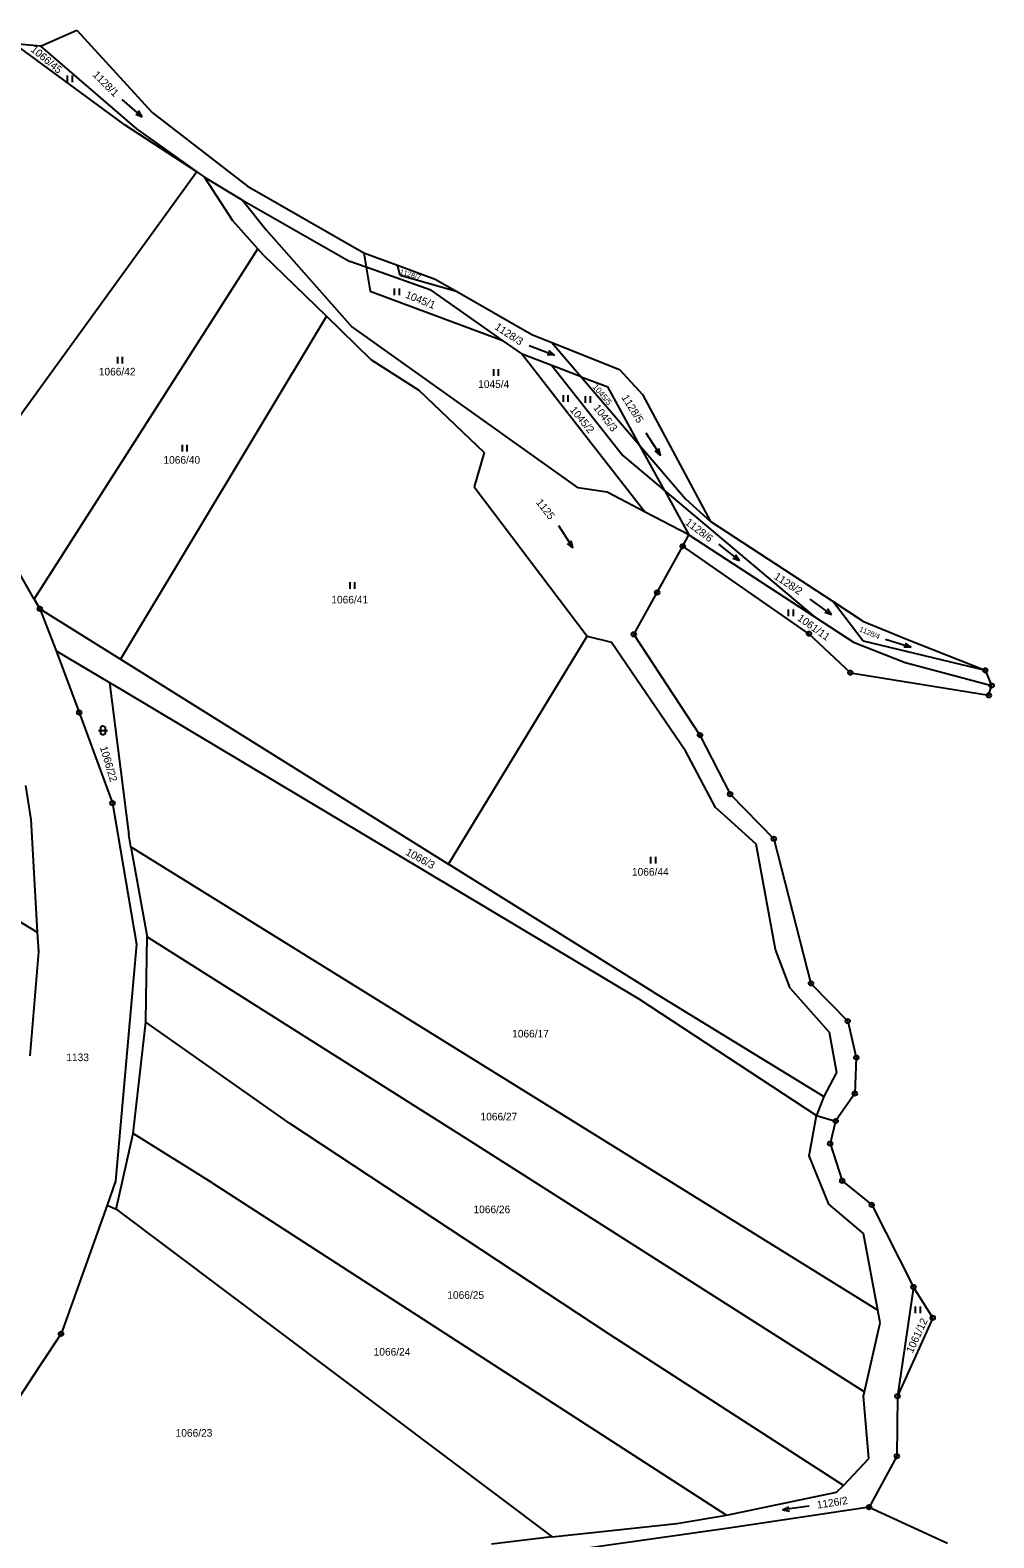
# Model space of a CAD drawing. Extents: x -794142 to -791199, y -1109267 to -1105626.
# Drawn here: x -791448.6 to -791232.9, y -1108817.8 to -1108480.5 of the extents above; entities that cross this region are included whole.
import ezdxf

# ---------------------------------------------------------------- set-up
doc = ezdxf.new("R2010")
doc.units = 0
for name, color, linetype in [('Vrstva 1', 7, 'Continuous'), ('Vrstva 14', 7, 'Continuous'), ('Vrstva 23', 7, 'Continuous'), ('Vrstva 28', 7, 'Continuous'), ('Vrstva 4', 7, 'Continuous')]:
    doc.layers.add(name, color=color, linetype=linetype)

msp = doc.modelspace()

# ---------------------------------------------------------------- linework, layer by layer
at = {"layer": 'Vrstva 1'}
for p, q in [((-791427.3, -1108501.83), (-791452.02, -1108483.63)), ((-791446.22, -1108484.1), (-791424.74, -1108502.61)), ((-791411.23, -1108512.26), (-791427.3, -1108501.83)), ((-791424.74, -1108502.61), (-791411.23, -1108512.26)), ((-791411.23, -1108512.26), (-791462.13, -1108582.4)), ((-791411.23, -1108512.26), (-791409.56, -1108513.46)), ((-791409.56, -1108513.46), (-791401.01, -1108518.59)), ((-791403.21, -1108523.17), (-791409.56, -1108513.46)), ((-791401.01, -1108518.59), (-791395.75, -1108525.23)), ((-791401.01, -1108518.59), (-791377, -1108532.27)), ((-791397.61, -1108529.42), (-791403.21, -1108523.17)), ((-791395.75, -1108525.23), (-791376.56, -1108546.87)), ((-791447.63, -1108607.79), (-791397.61, -1108529.42)), ((-791396.4, -1108530.77), (-791397.61, -1108529.42)), ((-791382.28, -1108544.53), (-791396.4, -1108530.77)), ((-791373.88, -1108530.37), (-791373.36, -1108533.57)), ((-791373.36, -1108533.57), (-791377, -1108532.27)), ((-791358.93, -1108538.72), (-791373.36, -1108533.57)), ((-791373.36, -1108533.57), (-791372.49, -1108538.94)), ((-791365.8, -1108535.45), (-791366.34, -1108533.14)), ((-791352.97, -1108539.08), (-791365.8, -1108535.45)), ((-791372.49, -1108538.94), (-791342.99, -1108549.86)), ((-791358.93, -1108538.72), (-791342.99, -1108549.86)), ((-791382.28, -1108544.53), (-791428.37, -1108621.22)), ((-791372.33, -1108554.23), (-791382.28, -1108544.53)), ((-791376.56, -1108546.87), (-791325.99, -1108582.88)), ((-791342.99, -1108549.86), (-791338.45, -1108553.03)), ((-791331.82, -1108550.39), (-791325.27, -1108558.06)), ((-791372.33, -1108554.23), (-791361.56, -1108561.06)), ((-791331.87, -1108555.54), (-791338.45, -1108553.03)), ((-791338.45, -1108553.03), (-791323.6, -1108572.11)), ((-791331.87, -1108555.54), (-791315.93, -1108575.68)), ((-791325.27, -1108558.06), (-791331.87, -1108555.54)), ((-791361.56, -1108561.06), (-791346.94, -1108574.99)), ((-791325.27, -1108558.06), (-791312.12, -1108573.45)), ((-791325.27, -1108558.06), (-791319.32, -1108560.33)), ((-791312.12, -1108573.45), (-791319.32, -1108560.33)), ((-791323.6, -1108572.11), (-791310.94, -1108588.33)), ((-791306.58, -1108583.55), (-791312.12, -1108573.45)), ((-791312.12, -1108573.45), (-791301.92, -1108585.39)), ((-791346.94, -1108574.99), (-791349.24, -1108582.69)), ((-791315.93, -1108575.68), (-791306.58, -1108583.55)), ((-791447.63, -1108607.79), (-791462.13, -1108582.4)), ((-791349.24, -1108582.69), (-791323.91, -1108616.12)), ((-791319.49, -1108583.87), (-791325.99, -1108582.88)), ((-791310.94, -1108588.33), (-791319.49, -1108583.87)), ((-791306.58, -1108583.55), (-791301.16, -1108593.44)), ((-791306.58, -1108583.55), (-791273.14, -1108611.72)), ((-791301.16, -1108593.44), (-791310.94, -1108588.33)), ((-791301.92, -1108585.39), (-791296.3, -1108590.48)), ((-791302.56, -1108595.98), (-791301.16, -1108593.44)), ((-791301.16, -1108593.44), (-791273.14, -1108611.72)), ((-791447.63, -1108607.79), (-791446.38, -1108609.97)), ((-791268.84, -1108608.45), (-791262.15, -1108617.17)), ((-791446.38, -1108609.97), (-791428.37, -1108621.22)), ((-791446.38, -1108609.97), (-791442.72, -1108619.38)), ((-791273.14, -1108611.72), (-791264.35, -1108617.45)), ((-791354.93, -1108667.11), (-791323.91, -1108616.12)), ((-791323.91, -1108616.12), (-791318.45, -1108617.47)), ((-791318.45, -1108617.47), (-791302.04, -1108641.62)), ((-791264.35, -1108617.45), (-791252.76, -1108621.95)), ((-791262.15, -1108617.17), (-791234.86, -1108623.73)), ((-791442.72, -1108619.38), (-791430.81, -1108626.43)), ((-791442.72, -1108619.38), (-791437.57, -1108633.18)), ((-791428.37, -1108621.22), (-791354.93, -1108667.11)), ((-791252.76, -1108621.95), (-791248.84, -1108623)), ((-791248.84, -1108623), (-791233.44, -1108627.13)), ((-791430.81, -1108626.43), (-791427.9, -1108628.17)), ((-791430.81, -1108626.43), (-791426.49, -1108660.51)), ((-791427.9, -1108628.17), (-791312.39, -1108697.23)), ((-791532.37, -1108630.01), (-791446.95, -1108682.34)), ((-791437.57, -1108633.18), (-791430.12, -1108653.46)), ((-791295.18, -1108654.41), (-791302.04, -1108641.62)), ((-791449.61, -1108649.48), (-791448.39, -1108657.12)), ((-791430.12, -1108653.46), (-791424.78, -1108685.01)), ((-791292.45, -1108656.87), (-791295.18, -1108654.41)), ((-791448.39, -1108657.12), (-791446.95, -1108682.34)), ((-791286.09, -1108662.61), (-791292.45, -1108656.87)), ((-791426, -1108663.21), (-791426.49, -1108660.51)), ((-791426, -1108663.21), (-791422.34, -1108683.38)), ((-791426, -1108663.21), (-791258.88, -1108766.87)), ((-791281.83, -1108686.19), (-791286.09, -1108662.61)), ((-791309.12, -1108695.74), (-791354.93, -1108667.11)), ((-791446.95, -1108682.34), (-791446.7, -1108686.74)), ((-791424.78, -1108685.01), (-791429.43, -1108738.03)), ((-791422.56, -1108697.06), (-791422.34, -1108683.38)), ((-791422.34, -1108683.38), (-791350.23, -1108728.91)), ((-791278.5, -1108694.84), (-791281.83, -1108686.19)), ((-791446.7, -1108686.74), (-791448.66, -1108709.97)), ((-791309.12, -1108695.74), (-791270.97, -1108719.08)), ((-791278.5, -1108694.84), (-791269.76, -1108704.68)), ((-791422.64, -1108702.44), (-791422.56, -1108697.06)), ((-791312.39, -1108697.23), (-791272.6, -1108723.32)), ((-791425.51, -1108727.35), (-791422.64, -1108702.44)), ((-791390.48, -1108725.11), (-791422.64, -1108702.44)), ((-791269.76, -1108704.68), (-791268.17, -1108713.72)), ((-791268.17, -1108713.72), (-791270.97, -1108719.08)), ((-791270.97, -1108719.08), (-791272.6, -1108723.32)), ((-791318.75, -1108772.36), (-791390.48, -1108725.11)), ((-791274.25, -1108732.36), (-791272.6, -1108723.32)), ((-791272.6, -1108723.32), (-791268.34, -1108724.56)), ((-791429.33, -1108744.29), (-791425.51, -1108727.35)), ((-791407.81, -1108738.38), (-791425.51, -1108727.35)), ((-791350.23, -1108728.91), (-791261.91, -1108785.1)), ((-791269.88, -1108743.18), (-791274.25, -1108732.36)), ((-791429.43, -1108738.03), (-791431.31, -1108743.39)), ((-791407.81, -1108738.38), (-791292.77, -1108812.71)), ((-791431.31, -1108743.39), (-791441.64, -1108772.15)), ((-791431.31, -1108743.39), (-791429.33, -1108744.29)), ((-791262.09, -1108749.73), (-791269.88, -1108743.18)), ((-791429.33, -1108744.29), (-791331.75, -1108817.59)), ((-791258.88, -1108766.87), (-791262.09, -1108749.73)), ((-791250.93, -1108761.68), (-791254.49, -1108786.11)), ((-791258.35, -1108769.67), (-791258.88, -1108766.87)), ((-791261.91, -1108785.1), (-791258.35, -1108769.67)), ((-791446.31, -1108779.26), (-791441.64, -1108772.15)), ((-791266.58, -1108806.07), (-791318.75, -1108772.36)), ((-791459, -1108798.61), (-791446.31, -1108779.26)), ((-791262.14, -1108786.09), (-791261.91, -1108785.1)), ((-791260.91, -1108800.07), (-791262.14, -1108786.09)), ((-791266.58, -1108806.07), (-791260.91, -1108800.07)), ((-791292.77, -1108812.71), (-791268.14, -1108807.57)), ((-791268.14, -1108807.57), (-791266.58, -1108806.07)), ((-791260.86, -1108810.93), (-791292.25, -1108815.59)), ((-791303.85, -1108814.58), (-791292.77, -1108812.71)), ((-791331.75, -1108817.59), (-791345.32, -1108819.21)), ((-791292.25, -1108815.59), (-791338.01, -1108822.07)), ((-791331.75, -1108817.59), (-791303.85, -1108814.58))]:
    msp.add_line(p, q, dxfattribs=at)
at = {"layer": 'Vrstva 23'}
for p, q in [((-791440.16, -1108492.16), (-791440.16, -1108490.66)), ((-791439.16, -1108490.66), (-791439.16, -1108492.16)), ((-791428.016, -1108496.044), (-791423.483, -1108499.975)), ((-791423.483, -1108499.975), (-791424.944, -1108499.37)), ((-791423.483, -1108499.975), (-791424.289, -1108498.614)), ((-791367.02, -1108539.81), (-791367.02, -1108538.31)), ((-791366.02, -1108538.31), (-791366.02, -1108539.81)), ((-791336.871, -1108551.066), (-791331.268, -1108553.213)), ((-791428.95, -1108555.08), (-791428.95, -1108553.58)), ((-791427.95, -1108553.58), (-791427.95, -1108555.08)), ((-791331.268, -1108553.213), (-791332.848, -1108553.143)), ((-791331.268, -1108553.213), (-791332.49, -1108552.209)), ((-791344.81, -1108557.87), (-791344.81, -1108556.37)), ((-791343.81, -1108556.37), (-791343.81, -1108557.87)), ((-791329.26, -1108563.68), (-791329.26, -1108562.18)), ((-791328.26, -1108562.18), (-791328.26, -1108563.68)), ((-791324.27, -1108563.88), (-791324.27, -1108562.38)), ((-791323.27, -1108562.38), (-791323.27, -1108563.88)), ((-791310.789, -1108570.627), (-791307.51, -1108575.652)), ((-791414.48, -1108574.82), (-791414.48, -1108573.32)), ((-791413.48, -1108573.32), (-791413.48, -1108574.82)), ((-791307.51, -1108575.652), (-791308.748, -1108574.669)), ((-791307.51, -1108575.652), (-791307.911, -1108574.122)), ((-791330.379, -1108591.307), (-791327.1, -1108596.332)), ((-791327.1, -1108596.332), (-791327.501, -1108594.802)), ((-791327.1, -1108596.332), (-791328.338, -1108595.349)), ((-791294.578, -1108595.535), (-791289.861, -1108599.244)), ((-791289.861, -1108599.244), (-791290.731, -1108597.924)), ((-791289.861, -1108599.244), (-791291.349, -1108598.71)), ((-791376.96, -1108605.5), (-791376.96, -1108604)), ((-791375.96, -1108604), (-791375.96, -1108605.5)), ((-791274.119, -1108607.804), (-791269.24, -1108611.295)), ((-791278.85, -1108611.62), (-791278.85, -1108610.12)), ((-791277.85, -1108610.12), (-791277.85, -1108611.62)), ((-791269.24, -1108611.295), (-791270.751, -1108610.829)), ((-791269.24, -1108611.295), (-791270.169, -1108610.016)), ((-791257.176, -1108616.733), (-791251.463, -1108618.566)), ((-791251.463, -1108618.566), (-791253.044, -1108618.584)), ((-791251.463, -1108618.566), (-791252.738, -1108617.632)), ((-791433.27, -1108637.18), (-791431.27, -1108637.18)), ((-791432.77, -1108636.58), (-791432.67, -1108636.38)), ((-791432.77, -1108637.78), (-791432.77, -1108636.58)), ((-791432.67, -1108637.98), (-791432.77, -1108637.78)), ((-791432.67, -1108636.38), (-791432.57, -1108636.28)), ((-791432.57, -1108638.08), (-791432.67, -1108637.98)), ((-791432.57, -1108636.28), (-791432.37, -1108636.18)), ((-791432.37, -1108638.18), (-791432.57, -1108638.08)), ((-791432.37, -1108636.18), (-791432.17, -1108636.18)), ((-791432.17, -1108638.18), (-791432.37, -1108638.18)), ((-791432.17, -1108636.18), (-791431.97, -1108636.28)), ((-791431.97, -1108638.08), (-791432.17, -1108638.18)), ((-791431.97, -1108636.28), (-791431.87, -1108636.38)), ((-791431.87, -1108637.98), (-791431.97, -1108638.08)), ((-791431.87, -1108636.38), (-791431.77, -1108636.58)), ((-791431.77, -1108637.78), (-791431.87, -1108637.98)), ((-791431.77, -1108636.58), (-791431.77, -1108637.78)), ((-791309.66, -1108666.96), (-791309.66, -1108665.46)), ((-791308.66, -1108665.46), (-791308.66, -1108666.96)), ((-791250.45, -1108767.56), (-791250.45, -1108766.06)), ((-791249.45, -1108766.06), (-791249.45, -1108767.56)), ((-791274.281, -1108810.685), (-791280.218, -1108811.554)), ((-791280.218, -1108811.554), (-791278.806, -1108810.842)), ((-791280.218, -1108811.554), (-791278.661, -1108811.831))]:
    msp.add_line(p, q, dxfattribs=at)
at = {"layer": 'Vrstva 28'}
for centre, radius in [((-791302.56, -1108595.98), 0.5), ((-791302.56, -1108595.98), 0.01), ((-791308.28, -1108606.32), 0.5), ((-791308.28, -1108606.32), 0.01), ((-791446.38, -1108609.97), 0.5), ((-791446.38, -1108609.97), 0.01), ((-791313.49, -1108615.69), 0.5), ((-791274.31, -1108615.54), 0.5), ((-791313.49, -1108615.69), 0.01), ((-791274.31, -1108615.54), 0.01), ((-791265.05, -1108624.27), 0.5), ((-791265.05, -1108624.27), 0.01), ((-791234.86, -1108623.73), 0.5), ((-791234.86, -1108623.73), 0.01), ((-791234.07, -1108629.32), 0.5), ((-791233.44, -1108627.13), 0.5), ((-791233.44, -1108627.13), 0.01), ((-791234.07, -1108629.32), 0.01), ((-791437.57, -1108633.18), 0.5), ((-791437.57, -1108633.18), 0.01), ((-791298.69, -1108638.22), 0.5), ((-791298.69, -1108638.22), 0.01), ((-791291.93, -1108651.43), 0.5), ((-791291.93, -1108651.43), 0.01), ((-791430.12, -1108653.46), 0.5), ((-791430.12, -1108653.46), 0.01), ((-791282.18, -1108661.41), 0.5), ((-791282.18, -1108661.41), 0.01), ((-791273.86, -1108693.76), 0.5), ((-791273.86, -1108693.76), 0.01), ((-791265.63, -1108702.19), 0.5), ((-791265.63, -1108702.19), 0.01), ((-791263.72, -1108710.35), 0.5), ((-791263.72, -1108710.35), 0.01), ((-791264.03, -1108718.41), 0.5), ((-791264.03, -1108718.41), 0.01), ((-791268.34, -1108724.56), 0.5), ((-791268.34, -1108724.56), 0.01), ((-791269.55, -1108729.6), 0.5), ((-791269.55, -1108729.6), 0.01), ((-791266.86, -1108737.93), 0.5), ((-791266.86, -1108737.93), 0.01), ((-791260.26, -1108743.31), 0.5), ((-791260.26, -1108743.31), 0.01), ((-791250.93, -1108761.68), 0.5), ((-791250.93, -1108761.68), 0.01), ((-791246.61, -1108768.57), 0.5), ((-791246.61, -1108768.57), 0.01), ((-791441.64, -1108772.15), 0.5), ((-791441.64, -1108772.15), 0.01), ((-791254.49, -1108786.11), 0.5), ((-791254.49, -1108786.11), 0.01), ((-791254.63, -1108799.53), 0.5), ((-791254.63, -1108799.53), 0.01), ((-791260.86, -1108810.93), 0.5), ((-791260.86, -1108810.93), 0.01)]:
    msp.add_circle(centre, radius, dxfattribs=at)
at = {"layer": 'Vrstva 4'}
for p, q in [((-791446.22, -1108484.1), (-791452.02, -1108483.63)), ((-791446.22, -1108484.1), (-791438.1, -1108480.54)), ((-791438.1, -1108480.54), (-791421.24, -1108498.98)), ((-791421.24, -1108498.98), (-791399.96, -1108515.43)), ((-791399.96, -1108515.43), (-791373.88, -1108530.37)), ((-791373.88, -1108530.37), (-791366.34, -1108533.14)), ((-791366.34, -1108533.14), (-791357.97, -1108536.22)), ((-791357.97, -1108536.22), (-791352.97, -1108539.08)), ((-791352.97, -1108539.08), (-791336.31, -1108548.59)), ((-791336.31, -1108548.59), (-791331.82, -1108550.39)), ((-791331.82, -1108550.39), (-791316.68, -1108556.45)), ((-791316.68, -1108556.45), (-791311.56, -1108562.07)), ((-791311.56, -1108562.07), (-791296.3, -1108590.48)), ((-791268.84, -1108608.45), (-791296.3, -1108590.48)), ((-791308.28, -1108606.32), (-791302.56, -1108595.98)), ((-791274.31, -1108615.54), (-791302.56, -1108595.98)), ((-791313.49, -1108615.69), (-791308.28, -1108606.32)), ((-791262.27, -1108612.75), (-791268.84, -1108608.45)), ((-791262.27, -1108612.75), (-791252.25, -1108616.85)), ((-791313.49, -1108615.69), (-791298.69, -1108638.22)), ((-791265.05, -1108624.27), (-791274.31, -1108615.54)), ((-791252.25, -1108616.85), (-791234.86, -1108623.73)), ((-791265.05, -1108624.27), (-791234.07, -1108629.32)), ((-791234.86, -1108623.73), (-791233.44, -1108627.13)), ((-791234.07, -1108629.32), (-791233.44, -1108627.13)), ((-791298.69, -1108638.22), (-791291.93, -1108651.43)), ((-791291.93, -1108651.43), (-791282.18, -1108661.41)), ((-791282.18, -1108661.41), (-791273.86, -1108693.76)), ((-791273.86, -1108693.76), (-791265.63, -1108702.19)), ((-791265.63, -1108702.19), (-791263.72, -1108710.35)), ((-791263.72, -1108710.35), (-791264.03, -1108718.41)), ((-791264.03, -1108718.41), (-791268.34, -1108724.56)), ((-791268.34, -1108724.56), (-791269.55, -1108729.6)), ((-791269.55, -1108729.6), (-791266.86, -1108737.93)), ((-791266.86, -1108737.93), (-791260.26, -1108743.31)), ((-791260.26, -1108743.31), (-791250.93, -1108761.68)), ((-791246.61, -1108768.57), (-791250.93, -1108761.68)), ((-791246.61, -1108768.57), (-791254.49, -1108786.11)), ((-791254.49, -1108786.11), (-791254.63, -1108799.53)), ((-791254.63, -1108799.53), (-791260.86, -1108810.93)), ((-791260.86, -1108810.93), (-791243.32, -1108818.98))]:
    msp.add_line(p, q, dxfattribs=at)

# ---------------------------------------------------------------- texts
at = {"layer": 'Vrstva 14'}
for s, height, rotation, p in [('1066/45', 1.7, 320.2578, (-791448.579, -1108485.12)), ('1128/1', 1.7, 315.27846, (-791434.693, -1108490.67)), ('1128/7', 1.14, 343.40193, (-791365.957, -1108535.033)), ('1045/1', 1.7, 338.13135, (-791364.756, -1108540.352)), ('1128/3', 1.7, 326.62647, (-791344.777, -1108547.303)), ('1045/5', 1.34, 310.15602, (-791322.814, -1108560.394)), ('1045/3', 1.7, 308.2563, (-791322.642, -1108565.069)), ('1128/5', 1.7, 301.69314, (-791316.292, -1108562.699)), ('1045/2', 1.7, 309.51045, (-791327.917, -1108565.54)), ('1125', 1.7, 307.78812, (-791335.461, -1108586.204)), ('1128/6', 1.7, 322.78428, (-791302.141, -1108590.968)), ('1128/2', 1.7, 326.62647, (-791282.29, -1108603.134)), ('1061/11', 1.7, 324.29961, (-791277.05, -1108612.405)), ('1128/4', 1.14, 337.11291, (-791263.155, -1108614.946)), ('1066/22', 1.7, 286.5708, (-791432.955, -1108640.975)), ('1066/3', 1.7, 331.32591, (-791364.698, -1108664.904)), ('1061/12', 1.7, 65.19609, (-791251.125, -1108776.614)), ('1126/2', 1.7, 9.01053, (-791272.39, -1108811.278))]:
    msp.add_text(s, height=height, rotation=rotation, dxfattribs=at).set_placement(p)
for s, p in [('1066/42', (-791433.198, -1108557.78)), ('1045/4', (-791348.31, -1108560.57)), ('1066/40', (-791418.737, -1108577.52)), ('1066/41', (-791381.171, -1108608.77)), ('1066/44', (-791313.904, -1108669.66)), ('1066/17', (-791340.712, -1108705.86)), ('1133', (-791440.453, -1108711.15)), ('1066/27', (-791347.789, -1108724.41)), ('1066/26', (-791349.362, -1108745.17)), ('1066/25', (-791355.218, -1108764.32)), ('1066/24', (-791371.698, -1108777.02)), ('1066/23', (-791416.002, -1108795.16))]:
    msp.add_text(s, height=1.7, dxfattribs=at).set_placement(p)

doc.saveas('drawing.dxf')
